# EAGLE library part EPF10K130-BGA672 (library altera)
EPF10K130 FLEX 10K family
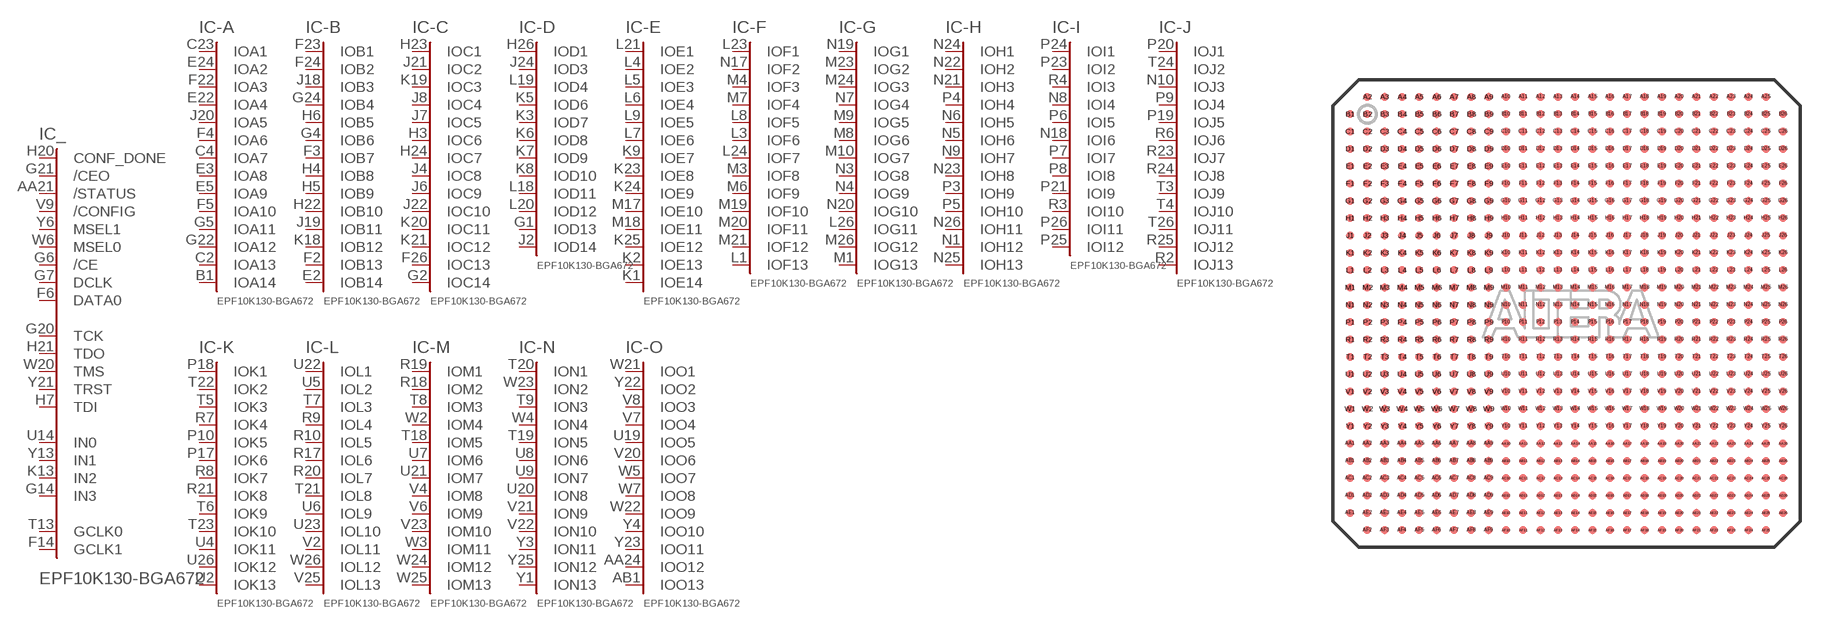
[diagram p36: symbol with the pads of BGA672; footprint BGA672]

Designator prefix IC; gates _=130E672C -A=A14-130E -B=B14-130E -C=C14-130E -D=D14-130E -E=E14-130E -F=F13-130E -G=G13-130E -H=H13-130E -I=I12-130E -J=J13-130E -K=K13-130E -L=L13-130E -M=M13-130E -N=N13-130E -O=O13-130E -P=P13-130E -1=51-130E -2=92-130E -3=133-130E -4=174-130E -5=221-130E -6=261-130E -7=301-130E -8=344-130E -9=384-130E -10=432-130E -11=472-130E -12=513-130E -13=524-130E G1=GND G2=GND G3=GND G4=GND G5=GND G6=GND G7=GND G8=GND G9=GND G10=GND G11=GND G12=GND G13=GND G14=GND G15=GND G16=GND G17=GND G18=GND G19=GND G20=GND G21=GND G22=GND G23=GND G24=GND G25=GND G26=GND G27=GND G28=GND G29=GND G30=GND G31=GND G32=GND G33=GND G34=GND G35=GND G36=GND G37=GND G38=GND G39=GND G40=GND G41=GND G42=GND G43=GND G44=GND G45=GND G46=GND G47=GND G48=GND G49=GND G50=GND G51=GND G52=GND G53=GND G54=GND G55=GND G56=GND G57=GND V1=VCCINT V2=VCCINT V3=VCCINT V4=VCCINT V5=VCCINT V6=VCCINT V7=VCCINT V8=VCCINT V9=VCCINT V10=VCCINT V11=VCCINT V12=VCCINT V13=VCCINT V14=VCCINT V15=VCCINT V16=VCCINT V17=VCCINT V18=VCCINT V19=VCCINT V20=VCCINT V21=VCCINT V22=VCCINT V23=VCCINT V24=VCCINT V25=VCCINT V26=VCCINT V27=VCCINT V28=VCCINT V29=VCCINT V30=VCCIO V31=VCCIO V32=VCCIO V33=VCCIO V34=VCCIO V35=VCCIO V36=VCCIO V37=VCCIO V38=VCCIO V39=VCCIO V40=VCCIO V41=VCCIO V42=VCCIO V43=VCCIO V44=VCCIO V45=VCCIO V46=VCCIO V47=VCCIO V48=VCCIO V49=VCCIO V50=VCCIO V51=VCCIO V52=VCCIO V53=VCCIO V54=VCCIO V55=VCCIO V56=VCCIO V57=VCCIO V58=VCCIO V59=VCCIO V60=VCCIO 1=NC 2=NC 3=NC 4=NC 5=NC 6=NC 7=NC 8=NC 9=NC 10=NC 11=NC 12=NC 13=NC 14=NC 15=NC 16=NC 17=NC 18=NC 19=NC 20=NC 21=NC 22=NC 23=NC 24=NC 25=NC 26=NC 27=NC 28=NC 29=NC 30=NC 31=NC 32=NC 33=NC 34=NC 35=NC 36=NC 37=NC 38=NC 39=NC 40=NC 41=NC 42=NC 43=NC 44=NC 45=NC 46=NC 47=NC 48=NC 49=NC 50=NC 51=NC 52=NC 53=NC 54=NC 55=NC 56=NC 57=NC 58=NC 59=NC 60=NC 61=NC 62=NC 63=NC 64=NC 65=NC 66=NC 67=NC 68=NC 69=NC 70=NC 71=NC 72=NC 73=NC 74=NC 75=NC 76=NC 77=NC 78=NC 79=NC 80=NC 81=NC 82=NC 83=NC 84=NC 85=NC 86=NC 87=NC 88=NC 89=NC 90=NC 91=NC 92=NC 93=NC 94=NC 95=NC 96=NC 97=NC 98=NC 99=NC 100=NC 101=NC 102=NC 103=NC 104=NC 105=NC 106=NC 107=NC 108=NC 109=NC 110=NC 111=NC 112=NC 113=NC 114=NC 115=NC 116=NC 117=NC 118=NC 119=NC 120=NC 121=NC 122=NC 123=NC 124=NC 125=NC 126=NC 127=NC 128=NC

## EPF10K130-BGA672 (MPN: EPF10K130EFC672-1; OC_FARNELL: unknown; OC_NEWARK: 51R8863)  [BGA672]
A2  G17:GND  pwr
A3  55:NC  nc
A4  56:NC  nc
A5  57:NC  nc
A6  58:NC  nc
A7  -2:IO64
A8  59:NC  nc
A9  60:NC  nc
A10  61:NC  nc
A11  62:NC  nc
A12  63:NC  nc
A13  64:NC  nc
A14  65:NC  nc
A15  66:NC  nc
A16  67:NC  nc
A17  68:NC  nc
A18  69:NC  nc
A19  70:NC  nc
A20  71:NC  nc
A21  72:NC  nc
A22  73:NC  nc
A23  74:NC  nc
A24  75:NC  nc
A25  G18:GND  pwr
AA1  1:NC  nc
AA2  2:NC  nc
AA3  -P:IOP12
AA4  -P:IOP5
AA5  -P:IOP3
AA6  -P:IOP4
AA7  -1:IO43
AA8  -2:IO71
AA9  -3:IO101
AA10  -3:IO131
AA11  -4:IO161
AA12  -6:IO223
AA13  G1:GND  pwr
AA14  -7:IO271
AA15  -8:IO323
AA16  -9:IO351
AA17  -10:IO392
AA18  -11:IO434
AA19  -12:IO483
AA20  -12:IO504
AA21  _:/STATUS  in
AA22  G2:GND  pwr
AA23  V1:VCC  pwr
AA24  -O:IOO12
AA25  3:NC  nc
AA26  V30:VCCIO  pwr
AB1  -O:IOO13
AB2  4:NC  nc
AB3  G3:GND  pwr
AB4  G4:GND  pwr
AB5  G5:GND  pwr
AB6  -1:IO14
AB7  -2:IO63
AB8  -2:IO81
AB9  -3:IO104
AB10  V2:VCC  pwr
AB11  -5:IO184
AB12  -6:IO224
AB13  -6:IO251
AB14  -7:IO284
AB15  -8:IO314
AB16  -9:IO354
AB17  -9:IO381
AB18  -10:IO414
AB19  -11:IO454
AB20  -12:IO481
AB21  -13:IO514
AB22  -13:IO521
AB23  G6:GND  pwr
AB24  G7:GND  pwr
AB25  5:NC  nc
AB26  6:NC  nc
AC1  7:NC  nc
AC2  8:NC  nc
AC3  G8:GND  pwr
AC4  -1:IO22
AC5  -1:IO21
AC6  -1:IO32
AC7  -2:IO61
AC8  G9:GND  pwr
AC9  -4:IO144
AC10  -4:IO164
AC11  -5:IO191
AC12  -6:IO234
AC13  -7:IO264
AC14  V3:VCC  pwr
AC15  -7:IO291
AC16  -8:IO342
AC17  -9:IO372
AC18  -10:IO402
AC19  -10:IO431
AC20  -11:IO461
AC21  -12:IO491
AC22  -12:IO511
AC23  -P:IOP6
AC24  G10:GND  pwr
AC25  9:NC  nc
AC26  10:NC  nc
AD1  -P:IOP13
AD2  11:NC  nc
AD3  -1:IO11
AD4  -1:IO31
AD5  -1:IO41
AD6  -1:IO51
AD7  -2:IO82
AD8  -3:IO121
AD9  -4:IO141
AD10  -4:IO172
AD11  -5:IO201
AD12  -6:IO231
AD13  G11:GND  pwr
AD14  -7:IO272
AD15  V31:VCCIO  pwr
AD16  -8:IO321
AD17  -9:IO364
AD18  G12:GND  pwr
AD19  -10:IO412
AD20  -11:IO442
AD21  -11:IO472
AD22  -12:IO503
AD23  -13:IO523
AD24  -P:IOP7
AD25  -P:IOP1
AD26  12:NC  nc
AE1  13:NC  nc
AE2  G13:GND  pwr
AE3  14:NC  nc
AE4  15:NC  nc
AE5  16:NC  nc
AE6  17:NC  nc
AE7  18:NC  nc
AE8  19:NC  nc
AE9  20:NC  nc
AE10  21:NC  nc
AE11  22:NC  nc
AE12  23:NC  nc
AE13  -6:IO261
AE14  24:NC  nc
AE15  25:NC  nc
AE16  26:NC  nc
AE17  27:NC  nc
AE18  -9:IO384
AE19  28:NC  nc
AE20  29:NC  nc
AE21  30:NC  nc
AE22  31:NC  nc
AE23  32:NC  nc
AE24  33:NC  nc
AE25  G14:GND  pwr
AE26  34:NC  nc
AF2  G15:GND  pwr
AF3  35:NC  nc
AF4  36:NC  nc
AF5  37:NC  nc
AF6  38:NC  nc
AF7  39:NC  nc
AF8  40:NC  nc
AF9  41:NC  nc
AF10  42:NC  nc
AF11  43:NC  nc
AF12  44:NC  nc
AF13  45:NC  nc
AF14  46:NC  nc
AF15  47:NC  nc
AF16  48:NC  nc
AF17  49:NC  nc
AF18  50:NC  nc
AF19  -10:IO394
AF20  51:NC  nc
AF21  52:NC  nc
AF22  -11:IO464
AF23  53:NC  nc
AF24  54:NC  nc
AF25  G16:GND  pwr
B1  -A:IOA14
B2  G19:GND  pwr
B3  76:NC  nc
B4  77:NC  nc
B5  78:NC  nc
B6  79:NC  nc
B7  80:NC  nc
B8  81:NC  nc
B9  82:NC  nc
B10  83:NC  nc
B11  84:NC  nc
B12  85:NC  nc
B13  86:NC  nc
B14  87:NC  nc
B15  -7:IO294
B16  88:NC  nc
B17  -8:IO344
B18  -10:IO393
B19  89:NC  nc
B20  90:NC  nc
B21  91:NC  nc
B22  92:NC  nc
B23  93:NC  nc
B24  94:NC  nc
B25  G20:GND  pwr
B26  95:NC  nc
C1  96:NC  nc
C2  -A:IOA13
C3  G21:GND  pwr
C4  -A:IOA7
C5  -1:IO23
C6  -1:IO42
C7  -2:IO83
C8  V32:VCCIO  pwr
C9  -3:IO103
C10  G22:GND  pwr
C11  -5:IO182
C12  -5:IO212
C13  -6:IO252
C14  -7:IO274
C15  V33:VCCIO  pwr
C16  -8:IO322
C17  -9:IO362
C18  -10:IO391
C19  -10:IO422
C20  -11:IO463
C21  -11:IO471
C22  -12:IO513
C23  -A:IOA1
C24  G23:GND  pwr
C25  97:NC  nc
C26  98:NC  nc
D1  99:NC  nc
D2  100:NC  nc
D3  G24:GND  pwr
D4  G25:GND  pwr
D5  -1:IO12
D6  -1:IO24
D7  V34:VCCIO  pwr
D8  -2:IO72
D9  -3:IO122
D10  -4:IO153
D11  -5:IO192
D12  -6:IO222
D13  -7:IO262
D14  -7:IO282
D15  -7:IO293
D16  -8:IO333
D17  -9:IO371
D18  -10:IO403
D19  G26:GND  pwr
D20  -11:IO462
D21  -12:IO493
D22  -13:IO524
D23  G27:GND  pwr
D24  G28:GND  pwr
D25  101:NC  nc
D26  102:NC  nc
E1  103:NC  nc
E2  -B:IOB14
E3  -A:IOA8
E4  G29:GND  pwr
E5  -A:IOA9
E6  -1:IO13
E7  -2:IO52
E8  -2:IO73
E9  -3:IO93
E10  -3:IO133
E11  -4:IO173
E12  -5:IO221
E13  V4:VCC  pwr
E14  -7:IO283
E15  -8:IO312
E16  -9:IO352
E17  V5:VCC  pwr
E18  -11:IO433
E19  -11:IO453
E20  -12:IO482
E21  -12:IO501
E22  -A:IOA4
E23  G30:GND  pwr
E24  -A:IOA2
E25  104:NC  nc
E26  105:NC  nc
F1  106:NC  nc
F2  -B:IOB13
F3  -B:IOB7
F4  -A:IOA6
F5  -A:IOA10
F6  _:DATA0  in
F7  -3:IO102
F8  -2:IO62
F9  -3:IO132
F10  -4:IO142
F11  -4:IO171
F12  -5:IO213
F13  -6:IO253
F14  _:GCLK1  in
F15  -8:IO302
F16  -9:IO373
F17  -10:IO413
F18  -10:IO423
F19  -12:IO473
F20  -12:IO512
F21  -13:IO522
F22  -A:IOA3
F23  -B:IOB1
F24  -B:IOB2
F25  107:NC  nc
F26  -C:IOC13
G1  -D:IOD13
G2  -C:IOC14
G3  V35:VCCIO  pwr
G4  -B:IOB6
G5  -A:IOA11
G6  _:/CE  in
G7  _:DCLK  in
G8  -2:IO92
G9  -3:IO123
G10  -4:IO152
G11  -4:IO163
G12  -6:IO232
G13  -6:IO242
G14  _:IN3  in
G15  -8:IO313
G16  -9:IO383
G17  -10:IO432
G18  -11:IO441
G19  -12:IO502
G20  _:TCK
G21  _:/CEO  in
G22  -A:IOA12
G23  G31:GND  pwr
G24  -B:IOB4
G25  108:NC  nc
G26  109:NC  nc
H1  110:NC  nc
H2  V6:VCC  pwr
H3  -C:IOC6
H4  -B:IOB8
H5  -B:IOB9
H6  -B:IOB5
H7  _:TDI
H8  -3:IO112
H9  -1:IO33
H10  -2:IO84
H11  -4:IO162
H12  -5:IO193
H13  -6:IO233
H14  -7:IO273
H15  -8:IO343
H16  -9:IO382
H17  -11:IO443
H18  -11:IO452
H19  -12:IO492
H20  _:CONF_DONE  in
H21  _:TDO
H22  -B:IOB10
H23  -C:IOC1
H24  -C:IOC7
H25  V7:VCC  pwr
H26  -D:IOD1
J1  111:NC  nc
J2  -D:IOD14
J3  V36:VCCIO  pwr
J4  -C:IOC8
J5  G32:GND  pwr
J6  -C:IOC9
J7  -C:IOC5
J8  -C:IOC4
J9  -4:IO143
J10  -1:IO34
J11  -2:IO53
J12  -5:IO203
J13  -7:IO263
J14  -6:IO243
J15  -9:IO353
J16  -10:IO411
J17  V37:VCCIO  pwr
J18  -B:IOB3
J19  -B:IOB11
J20  -A:IOA5
J21  -C:IOC2
J22  -C:IOC10
J23  G33:GND  pwr
J24  -D:IOD3
J25  112:NC  nc
J26  113:NC  nc
K1  -E:IOE14
K2  -E:IOE13
K3  -D:IOD7
K4  G34:GND  pwr
K5  -D:IOD6
K6  -D:IOD8
K7  -D:IOD9
K8  -D:IOD10
K9  -E:IOE7
K10  G35:GND  pwr
K11  V38:VCCIO  pwr
K12  -5:IO183
K13  _:IN2  in
K14  -5:IO202
K15  -9:IO363
K16  V8:VCC  pwr
K17  G36:GND  pwr
K18  -B:IOB12
K19  -C:IOC3
K20  -C:IOC11
K21  -C:IOC12
K22  V39:VCCIO  pwr
K23  -E:IOE8
K24  -E:IOE9
K25  -E:IOE12
K26  114:NC  nc
L1  -F:IOF13
L2  115:NC  nc
L3  -F:IOF6
L4  -E:IOE2
L5  -E:IOE3
L6  -E:IOE4
L7  -E:IOE6
L8  -F:IOF5
L9  -E:IOE5
L10  V9:VCC  pwr
L11  G37:GND  pwr
L12  V10:VCC  pwr
L13  V40:VCCIO  pwr
L14  V11:VCC  pwr
L15  V41:VCCIO  pwr
L16  G38:GND  pwr
L17  V12:VCC  pwr
L18  -D:IOD11
L19  -D:IOD4
L20  -D:IOD12
L21  -E:IOE1
L22  G39:GND  pwr
L23  -F:IOF1
L24  -F:IOF7
L25  116:NC  nc
L26  -G:IOG11
M1  -G:IOG13
M2  V13:VCC  pwr
M3  -F:IOF8
M4  -F:IOF3
M5  G40:GND  pwr
M6  -F:IOF9
M7  -F:IOF4
M8  -G:IOG6
M9  -G:IOG5
M10  -G:IOG7
M11  V42:VCCIO  pwr
M12  G41:GND  pwr
M13  V43:VCCIO  pwr
M14  G42:GND  pwr
M15  G43:GND  pwr
M16  V44:VCCIO  pwr
M17  -E:IOE10
M18  -E:IOE11
M19  -F:IOF10
M20  -F:IOF11
M21  -F:IOF12
M22  V45:VCCIO  pwr
M23  -G:IOG2
M24  -G:IOG3
M25  V14:VCC  pwr
M26  -G:IOG12
N1  -H:IOH12
N2  117:NC  nc
N3  -G:IOG8
N4  -G:IOG9
N5  -H:IOH6
N6  -H:IOH5
N7  -G:IOG4
N8  -I:IOI4
N9  -H:IOH7
N10  -J:IOJ3
N11  V15:VCC  pwr
N12  V16:VCC  pwr
N13  G44:GND  pwr
N14  G45:GND  pwr
N15  V17:VCC  pwr
N16  V46:VCCIO  pwr
N17  -F:IOF2
N18  -I:IOI6
N19  -G:IOG1
N20  -G:IOG10
N21  -H:IOH3
N22  -H:IOH2
N23  -H:IOH8
N24  -H:IOH1
N25  -H:IOH13
N26  -H:IOH11
P1  118:NC  nc
P2  119:NC  nc
P3  -H:IOH9
P4  -H:IOH4
P5  -H:IOH10
P6  -I:IOI5
P7  -I:IOI7
P8  -I:IOI8
P9  -J:IOJ4
P10  -K:IOK5
P11  V47:VCCIO  pwr
P12  V18:VCC  pwr
P13  G46:GND  pwr
P14  G47:GND  pwr
P15  V19:VCC  pwr
P16  V20:VCC  pwr
P17  -K:IOK6
P18  -K:IOK1
P19  -J:IOJ5
P20  -J:IOJ1
P21  -I:IOI9
P22  G48:GND  pwr
P23  -I:IOI2
P24  -I:IOI1
P25  -I:IOI12
P26  -I:IOI11
R1  120:NC  nc
R2  -J:IOJ13
R3  -I:IOI10
R4  -I:IOI3
R5  V48:VCCIO  pwr
R6  -J:IOJ6
R7  -K:IOK4
R8  -K:IOK7
R9  -L:IOL4
R10  -L:IOL5
R11  V49:VCCIO  pwr
R12  G49:GND  pwr
R13  V50:VCCIO  pwr
R14  V21:VCC  pwr
R15  G50:GND  pwr
R16  V51:VCCIO  pwr
R17  -L:IOL6
R18  -M:IOM2
R19  -M:IOM1
R20  -L:IOL7
R21  -K:IOK8
R22  V52:VCCIO  pwr
R23  -J:IOJ7
R24  -J:IOJ8
R25  -J:IOJ12
R26  121:NC  nc
T1  122:NC  nc
T2  V22:VCC  pwr
T3  -J:IOJ9
T4  -J:IOJ10
T5  -K:IOK3
T6  -K:IOK9
T7  -L:IOL3
T8  -M:IOM3
T9  -N:ION3
T10  V23:VCC  pwr
T11  G51:GND  pwr
T12  V24:VCC  pwr
T13  _:GCLK0  in
T14  V25:VCC  pwr
T15  V53:VCCIO  pwr
T16  G52:GND  pwr
T17  V26:VCC  pwr
T18  -M:IOM5
T19  -N:ION5
T20  -N:ION1
T21  -L:IOL8
T22  -K:IOK2
T23  -K:IOK10
T24  -J:IOJ2
T25  V27:VCC  pwr
T26  -J:IOJ11
U1  123:NC  nc
U2  -K:IOK13
U3  V54:VCCIO  pwr
U4  -K:IOK11
U5  -L:IOL2
U6  -L:IOL9
U7  -M:IOM6
U8  -N:ION6
U9  -N:ION7
U10  G53:GND  pwr
U11  V55:VCCIO  pwr
U12  -4:IO151
U13  -6:IO244
U14  _:IN0  in
U15  -7:IO301
U16  V28:VCC  pwr
U17  G54:GND  pwr
U18  -P:IOP8
U19  -O:IOO5
U20  -N:ION8
U21  -M:IOM7
U22  -L:IOL1
U23  -L:IOL10
U24  G55:GND  pwr
U25  124:NC  nc
U26  -K:IOK12
V1  125:NC  nc
V2  -L:IOL11
V3  G56:GND  pwr
V4  -M:IOM8
V5  V56:VCCIO  pwr
V6  -M:IOM9
V7  -O:IOO4
V8  -O:IOO3
V9  _:/CONFIG  in
V10  -3:IO111
V11  -4:IO154
V12  -5:IO204
V13  -6:IO241
V14  -8:IO303
V15  -8:IO331
V16  -10:IO421
V17  V57:VCCIO  pwr
V18  -P:IOP9
V19  -P:IOP10
V20  -O:IOO6
V21  -N:ION9
V22  -N:ION10
V23  -M:IOM10
V24  V58:VCCIO  pwr
V25  -L:IOL13
V26  126:NC  nc
W1  127:NC  nc
W2  -M:IOM4
W3  -M:IOM11
W4  -N:ION4
W5  -O:IOO7
W6  _:MSEL0  in
W7  -O:IOO8
W8  -P:IOP11
W9  -3:IO94
W10  -3:IO113
W11  -5:IO181
W12  -5:IO214
W13  -6:IO254
W14  -7:IO292
W15  -8:IO332
W16  -9:IO374
W17  -9:IO361
W18  -11:IO451
W19  -12:IO474
W20  _:TMS
W21  -O:IOO1
W22  -O:IOO9
W23  -N:ION2
W24  -M:IOM12
W25  -M:IOM13
W26  -L:IOL12
Y1  -N:ION13
Y2  V59:VCCIO  pwr
Y3  -N:ION11
Y4  -O:IOO10
Y5  G57:GND  pwr
Y6  _:MSEL1  in
Y7  V29:VCC  pwr
Y8  -2:IO74
Y9  -2:IO91
Y10  -3:IO124
Y11  -4:IO174
Y12  -5:IO211
Y13  _:IN1  in
Y14  -7:IO281
Y15  -8:IO311
Y16  -8:IO341
Y17  -10:IO401
Y18  -11:IO444
Y19  -12:IO494
Y20  -P:IOP2
Y21  _:TRST
Y22  -O:IOO2
Y23  -O:IOO11
Y24  V60:VCCIO  pwr
Y25  -N:ION12
Y26  128:NC  nc

## Footprint BGA672 (pad centres in mm)
Ball Grid Array
smd 0.45 x 0.45: A2 -11.5,12.5; A3 -10.5,12.5; A4 -9.5,12.5; A5 -8.5,12.5; A6 -7.5,12.5; A7 -6.5,12.5; A8 -5.5,12.5; A9 -4.5,12.5; A10 -3.5,12.5; A11 -2.5,12.5; A12 -1.5,12.5; A13 -0.5,12.5; A14 0.5,12.5; A15 1.5,12.5; A16 2.5,12.5; A17 3.5,12.5; A18 4.5,12.5; A19 5.5,12.5; A20 6.5,12.5; A21 7.5,12.5; A22 8.5,12.5; A23 9.5,12.5; A24 10.5,12.5; A25 11.5,12.5; AA1 -12.5,-7.5; AA2 -11.5,-7.5; AA3 -10.5,-7.5; AA4 -9.5,-7.5; AA5 -8.5,-7.5; AA6 -7.5,-7.5; AA7 -6.5,-7.5; AA8 -5.5,-7.5; AA9 -4.5,-7.5; AA10 -3.5,-7.5; AA11 -2.5,-7.5; AA12 -1.5,-7.5; AA13 -0.5,-7.5; AA14 0.5,-7.5; AA15 1.5,-7.5; AA16 2.5,-7.5; AA17 3.5,-7.5; AA18 4.5,-7.5; AA19 5.5,-7.5; AA20 6.5,-7.5; AA21 7.5,-7.5; AA22 8.5,-7.5; AA23 9.5,-7.5; AA24 10.5,-7.5; AA25 11.5,-7.5; AA26 12.5,-7.5; AB1 -12.5,-8.5; AB2 -11.5,-8.5; AB3 -10.5,-8.5; AB4 -9.5,-8.5; AB5 -8.5,-8.5; AB6 -7.5,-8.5; AB7 -6.5,-8.5; AB8 -5.5,-8.5; AB9 -4.5,-8.5; AB10 -3.5,-8.5; AB11 -2.5,-8.5; AB12 -1.5,-8.5; AB13 -0.5,-8.5; AB14 0.5,-8.5; AB15 1.5,-8.5; AB16 2.5,-8.5; AB17 3.5,-8.5; AB18 4.5,-8.5; AB19 5.5,-8.5; AB20 6.5,-8.5; AB21 7.5,-8.5; AB22 8.5,-8.5; AB23 9.5,-8.5; AB24 10.5,-8.5; AB25 11.5,-8.5; AB26 12.5,-8.5; AC1 -12.5,-9.5; AC2 -11.5,-9.5; AC3 -10.5,-9.5; AC4 -9.5,-9.5; AC5 -8.5,-9.5; AC6 -7.5,-9.5; AC7 -6.5,-9.5; AC8 -5.5,-9.5; AC9 -4.5,-9.5; AC10 -3.5,-9.5; AC11 -2.5,-9.5; AC12 -1.5,-9.5; AC13 -0.5,-9.5; AC14 0.5,-9.5; AC15 1.5,-9.5; AC16 2.5,-9.5; AC17 3.5,-9.5; AC18 4.5,-9.5; AC19 5.5,-9.5; AC20 6.5,-9.5; AC21 7.5,-9.5; AC22 8.5,-9.5; AC23 9.5,-9.5; AC24 10.5,-9.5; AC25 11.5,-9.5; AC26 12.5,-9.5; AD1 -12.5,-10.5; AD2 -11.5,-10.5; AD3 -10.5,-10.5; AD4 -9.5,-10.5; AD5 -8.5,-10.5; AD6 -7.5,-10.5; AD7 -6.5,-10.5; AD8 -5.5,-10.5; AD9 -4.5,-10.5; AD10 -3.5,-10.5; AD11 -2.5,-10.5; AD12 -1.5,-10.5; AD13 -0.5,-10.5; AD14 0.5,-10.5; AD15 1.5,-10.5; AD16 2.5,-10.5; AD17 3.5,-10.5; AD18 4.5,-10.5; AD19 5.5,-10.5; AD20 6.5,-10.5; AD21 7.5,-10.5; AD22 8.5,-10.5; AD23 9.5,-10.5; AD24 10.5,-10.5; AD25 11.5,-10.5; AD26 12.5,-10.5; AE1 -12.5,-11.5; AE2 -11.5,-11.5; AE3 -10.5,-11.5; AE4 -9.5,-11.5; AE5 -8.5,-11.5; AE6 -7.5,-11.5; AE7 -6.5,-11.5; AE8 -5.5,-11.5; AE9 -4.5,-11.5; AE10 -3.5,-11.5; AE11 -2.5,-11.5; AE12 -1.5,-11.5; AE13 -0.5,-11.5; AE14 0.5,-11.5; AE15 1.5,-11.5; AE16 2.5,-11.5; AE17 3.5,-11.5; AE18 4.5,-11.5; AE19 5.5,-11.5; AE20 6.5,-11.5; AE21 7.5,-11.5; AE22 8.5,-11.5; AE23 9.5,-11.5; AE24 10.5,-11.5; AE25 11.5,-11.5; AE26 12.5,-11.5; AF2 -11.5,-12.5; AF3 -10.5,-12.5; AF4 -9.5,-12.5; AF5 -8.5,-12.5; AF6 -7.5,-12.5; AF7 -6.5,-12.5; AF8 -5.5,-12.5; AF9 -4.5,-12.5; AF10 -3.5,-12.5; AF11 -2.5,-12.5; AF12 -1.5,-12.5; AF13 -0.5,-12.5; AF14 0.5,-12.5; AF15 1.5,-12.5; AF16 2.5,-12.5; AF17 3.5,-12.5; AF18 4.5,-12.5; AF19 5.5,-12.5; AF20 6.5,-12.5; AF21 7.5,-12.5; AF22 8.5,-12.5; AF23 9.5,-12.5; AF24 10.5,-12.5; AF25 11.5,-12.5; B1 -12.5,11.5; B2 -11.5,11.5; B3 -10.5,11.5; B4 -9.5,11.5; B5 -8.5,11.5; B6 -7.5,11.5; B7 -6.5,11.5; B8 -5.5,11.5; B9 -4.5,11.5; B10 -3.5,11.5; B11 -2.5,11.5; B12 -1.5,11.5; B13 -0.5,11.5; B14 0.5,11.5; B15 1.5,11.5; B16 2.5,11.5; B17 3.5,11.5; B18 4.5,11.5; B19 5.5,11.5; B20 6.5,11.5; B21 7.5,11.5; B22 8.5,11.5; B23 9.5,11.5; B24 10.5,11.5; B25 11.5,11.5; B26 12.5,11.5; C1 -12.5,10.5; C2 -11.5,10.5; C3 -10.5,10.5; C4 -9.5,10.5; C5 -8.5,10.5; C6 -7.5,10.5; C7 -6.5,10.5; C8 -5.5,10.5; C9 -4.5,10.5; C10 -3.5,10.5; C11 -2.5,10.5; C12 -1.5,10.5; C13 -0.5,10.5; C14 0.5,10.5; C15 1.5,10.5; C16 2.5,10.5; C17 3.5,10.5; C18 4.5,10.5; C19 5.5,10.5; C20 6.5,10.5; C21 7.5,10.5; C22 8.5,10.5; C23 9.5,10.5; C24 10.5,10.5; C25 11.5,10.5; C26 12.5,10.5; D1 -12.5,9.5; D2 -11.5,9.5; D3 -10.5,9.5; D4 -9.5,9.5; D5 -8.5,9.5; D6 -7.5,9.5; D7 -6.5,9.5; D8 -5.5,9.5; D9 -4.5,9.5; D10 -3.5,9.5; D11 -2.5,9.5; D12 -1.5,9.5; D13 -0.5,9.5; D14 0.5,9.5; D15 1.5,9.5; D16 2.5,9.5; D17 3.5,9.5; D18 4.5,9.5; D19 5.5,9.5; D20 6.5,9.5; D21 7.5,9.5; D22 8.5,9.5; D23 9.5,9.5; D24 10.5,9.5; D25 11.5,9.5; D26 12.5,9.5; E1 -12.5,8.5; E2 -11.5,8.5; E3 -10.5,8.5; E4 -9.5,8.5; E5 -8.5,8.5; E6 -7.5,8.5; E7 -6.5,8.5; E8 -5.5,8.5; E9 -4.5,8.5; E10 -3.5,8.5; E11 -2.5,8.5; E12 -1.5,8.5; E13 -0.5,8.5; E14 0.5,8.5; E15 1.5,8.5; E16 2.5,8.5; E17 3.5,8.5; E18 4.5,8.5; E19 5.5,8.5; E20 6.5,8.5; E21 7.5,8.5; E22 8.5,8.5; E23 9.5,8.5; E24 10.5,8.5; E25 11.5,8.5; E26 12.5,8.5; F1 -12.5,7.5; F2 -11.5,7.5; F3 -10.5,7.5; F4 -9.5,7.5; F5 -8.5,7.5; F6 -7.5,7.5; F7 -6.5,7.5; F8 -5.5,7.5; F9 -4.5,7.5; F10 -3.5,7.5; F11 -2.5,7.5; F12 -1.5,7.5; F13 -0.5,7.5; F14 0.5,7.5; F15 1.5,7.5; F16 2.5,7.5; F17 3.5,7.5; F18 4.5,7.5; F19 5.5,7.5; F20 6.5,7.5; F21 7.5,7.5; F22 8.5,7.5; F23 9.5,7.5; F24 10.5,7.5; F25 11.5,7.5; F26 12.5,7.5; G1 -12.5,6.5; G2 -11.5,6.5; G3 -10.5,6.5; G4 -9.5,6.5; G5 -8.5,6.5; G6 -7.5,6.5; G7 -6.5,6.5; G8 -5.5,6.5; G9 -4.5,6.5; G10 -3.5,6.5; G11 -2.5,6.5; G12 -1.5,6.5; G13 -0.5,6.5; G14 0.5,6.5; G15 1.5,6.5; G16 2.5,6.5; G17 3.5,6.5; G18 4.5,6.5; G19 5.5,6.5; G20 6.5,6.5; G21 7.5,6.5; G22 8.5,6.5; G23 9.5,6.5; G24 10.5,6.5; G25 11.5,6.5; G26 12.5,6.5; H1 -12.5,5.5; H2 -11.5,5.5; H3 -10.5,5.5; H4 -9.5,5.5; H5 -8.5,5.5; H6 -7.5,5.5; H7 -6.5,5.5; H8 -5.5,5.5; H9 -4.5,5.5; H10 -3.5,5.5; H11 -2.5,5.5; H12 -1.5,5.5; H13 -0.5,5.5; H14 0.5,5.5; H15 1.5,5.5; H16 2.5,5.5; H17 3.5,5.5; H18 4.5,5.5; H19 5.5,5.5; H20 6.5,5.5; H21 7.5,5.5; H22 8.5,5.5; H23 9.5,5.5; H24 10.5,5.5; H25 11.5,5.5; H26 12.5,5.5; J1 -12.5,4.5; J2 -11.5,4.5; J3 -10.5,4.5; J4 -9.5,4.5; J5 -8.5,4.5; J6 -7.5,4.5; J7 -6.5,4.5; J8 -5.5,4.5; J9 -4.5,4.5; J10 -3.5,4.5; J11 -2.5,4.5; J12 -1.5,4.5; J13 -0.5,4.5; J14 0.5,4.5; J15 1.5,4.5; J16 2.5,4.5; J17 3.5,4.5; J18 4.5,4.5; J19 5.5,4.5; J20 6.5,4.5; J21 7.5,4.5; J22 8.5,4.5; J23 9.5,4.5; J24 10.5,4.5; J25 11.5,4.5; J26 12.5,4.5; K1 -12.5,3.5; K2 -11.5,3.5; K3 -10.5,3.5; K4 -9.5,3.5; K5 -8.5,3.5; K6 -7.5,3.5; K7 -6.5,3.5; K8 -5.5,3.5; K9 -4.5,3.5; K10 -3.5,3.5; K11 -2.5,3.5; K12 -1.5,3.5; K13 -0.5,3.5; K14 0.5,3.5; K15 1.5,3.5; K16 2.5,3.5; K17 3.5,3.5; K18 4.5,3.5; K19 5.5,3.5; K20 6.5,3.5; K21 7.5,3.5; K22 8.5,3.5; K23 9.5,3.5; K24 10.5,3.5; K25 11.5,3.5; K26 12.5,3.5; L1 -12.5,2.5; L2 -11.5,2.5; L3 -10.5,2.5; L4 -9.5,2.5; L5 -8.5,2.5; L6 -7.5,2.5; L7 -6.5,2.5; L8 -5.5,2.5; L9 -4.5,2.5; L10 -3.5,2.5; L11 -2.5,2.5; L12 -1.5,2.5; L13 -0.5,2.5; L14 0.5,2.5; L15 1.5,2.5; L16 2.5,2.5; L17 3.5,2.5; L18 4.5,2.5; L19 5.5,2.5; L20 6.5,2.5; L21 7.5,2.5; L22 8.5,2.5; L23 9.5,2.5; L24 10.5,2.5; L25 11.5,2.5; L26 12.5,2.5; M1 -12.5,1.5; M2 -11.5,1.5; M3 -10.5,1.5; M4 -9.5,1.5; M5 -8.5,1.5; M6 -7.5,1.5; M7 -6.5,1.5; M8 -5.5,1.5; M9 -4.5,1.5; M10 -3.5,1.5; M11 -2.5,1.5; M12 -1.5,1.5; M13 -0.5,1.5; M14 0.5,1.5; M15 1.5,1.5; M16 2.5,1.5; M17 3.5,1.5; M18 4.5,1.5; M19 5.5,1.5; M20 6.5,1.5; M21 7.5,1.5; M22 8.5,1.5; M23 9.5,1.5; M24 10.5,1.5; M25 11.5,1.5; M26 12.5,1.5; N1 -12.5,0.5; N2 -11.5,0.5; N3 -10.5,0.5; N4 -9.5,0.5; N5 -8.5,0.5; N6 -7.5,0.5; N7 -6.5,0.5; N8 -5.5,0.5; N9 -4.5,0.5; N10 -3.5,0.5; N11 -2.5,0.5; N12 -1.5,0.5; N13 -0.5,0.5; N14 0.5,0.5; N15 1.5,0.5; N16 2.5,0.5; N17 3.5,0.5; N18 4.5,0.5; N19 5.5,0.5; N20 6.5,0.5; N21 7.5,0.5; N22 8.5,0.5; N23 9.5,0.5; N24 10.5,0.5; N25 11.5,0.5; N26 12.5,0.5; P1 -12.5,-0.5; P2 -11.5,-0.5; P3 -10.5,-0.5; P4 -9.5,-0.5; P5 -8.5,-0.5; P6 -7.5,-0.5; P7 -6.5,-0.5; P8 -5.5,-0.5; P9 -4.5,-0.5; P10 -3.5,-0.5; P11 -2.5,-0.5; P12 -1.5,-0.5; P13 -0.5,-0.5; P14 0.5,-0.5; P15 1.5,-0.5; P16 2.5,-0.5; P17 3.5,-0.5; P18 4.5,-0.5; P19 5.5,-0.5; P20 6.5,-0.5; P21 7.5,-0.5; P22 8.5,-0.5; P23 9.5,-0.5; P24 10.5,-0.5; P25 11.5,-0.5; P26 12.5,-0.5; R1 -12.5,-1.5; R2 -11.5,-1.5; R3 -10.5,-1.5; R4 -9.5,-1.5; R5 -8.5,-1.5; R6 -7.5,-1.5; R7 -6.5,-1.5; R8 -5.5,-1.5; R9 -4.5,-1.5; R10 -3.5,-1.5; R11 -2.5,-1.5; R12 -1.5,-1.5; R13 -0.5,-1.5; R14 0.5,-1.5; R15 1.5,-1.5; R16 2.5,-1.5; R17 3.5,-1.5; R18 4.5,-1.5; R19 5.5,-1.5; R20 6.5,-1.5; R21 7.5,-1.5; R22 8.5,-1.5; R23 9.5,-1.5; R24 10.5,-1.5; R25 11.5,-1.5; R26 12.5,-1.5; T1 -12.5,-2.5; T2 -11.5,-2.5; T3 -10.5,-2.5; T4 -9.5,-2.5; T5 -8.5,-2.5; T6 -7.5,-2.5; T7 -6.5,-2.5; T8 -5.5,-2.5; T9 -4.5,-2.5; T10 -3.5,-2.5; T11 -2.5,-2.5; T12 -1.5,-2.5; T13 -0.5,-2.5; T14 0.5,-2.5; T15 1.5,-2.5; T16 2.5,-2.5; T17 3.5,-2.5; T18 4.5,-2.5; T19 5.5,-2.5; T20 6.5,-2.5; T21 7.5,-2.5; T22 8.5,-2.5; T23 9.5,-2.5; T24 10.5,-2.5; T25 11.5,-2.5; T26 12.5,-2.5; U1 -12.5,-3.5; U2 -11.5,-3.5; U3 -10.5,-3.5; U4 -9.5,-3.5; U5 -8.5,-3.5; U6 -7.5,-3.5; U7 -6.5,-3.5; U8 -5.5,-3.5; U9 -4.5,-3.5; U10 -3.5,-3.5; U11 -2.5,-3.5; U12 -1.5,-3.5; U13 -0.5,-3.5; U14 0.5,-3.5; U15 1.5,-3.5; U16 2.5,-3.5; U17 3.5,-3.5; U18 4.5,-3.5; U19 5.5,-3.5; U20 6.5,-3.5; U21 7.5,-3.5; U22 8.5,-3.5; U23 9.5,-3.5; U24 10.5,-3.5; U25 11.5,-3.5; U26 12.5,-3.5; V1 -12.5,-4.5; V2 -11.5,-4.5; V3 -10.5,-4.5; V4 -9.5,-4.5; V5 -8.5,-4.5; V6 -7.5,-4.5; V7 -6.5,-4.5; V8 -5.5,-4.5; V9 -4.5,-4.5; V10 -3.5,-4.5; V11 -2.5,-4.5; V12 -1.5,-4.5; V13 -0.5,-4.5; V14 0.5,-4.5; V15 1.5,-4.5; V16 2.5,-4.5; V17 3.5,-4.5; V18 4.5,-4.5; V19 5.5,-4.5; V20 6.5,-4.5; V21 7.5,-4.5; V22 8.5,-4.5; V23 9.5,-4.5; V24 10.5,-4.5; V25 11.5,-4.5; V26 12.5,-4.5; W1 -12.5,-5.5; W2 -11.5,-5.5; W3 -10.5,-5.5; W4 -9.5,-5.5; W5 -8.5,-5.5; W6 -7.5,-5.5; W7 -6.5,-5.5; W8 -5.5,-5.5; W9 -4.5,-5.5; W10 -3.5,-5.5; W11 -2.5,-5.5; W12 -1.5,-5.5; W13 -0.5,-5.5; W14 0.5,-5.5; W15 1.5,-5.5; W16 2.5,-5.5; W17 3.5,-5.5; W18 4.5,-5.5; W19 5.5,-5.5; W20 6.5,-5.5; W21 7.5,-5.5; W22 8.5,-5.5; W23 9.5,-5.5; W24 10.5,-5.5; W25 11.5,-5.5; W26 12.5,-5.5; Y1 -12.5,-6.5; Y2 -11.5,-6.5; Y3 -10.5,-6.5; Y4 -9.5,-6.5; Y5 -8.5,-6.5; Y6 -7.5,-6.5; Y7 -6.5,-6.5; Y8 -5.5,-6.5; Y9 -4.5,-6.5; Y10 -3.5,-6.5; Y11 -2.5,-6.5; Y12 -1.5,-6.5; Y13 -0.5,-6.5; Y14 0.5,-6.5; Y15 1.5,-6.5; Y16 2.5,-6.5; Y17 3.5,-6.5; Y18 4.5,-6.5; Y19 5.5,-6.5; Y20 6.5,-6.5; Y21 7.5,-6.5; Y22 8.5,-6.5; Y23 9.5,-6.5; Y24 10.5,-6.5; Y25 11.5,-6.5; Y26 12.5,-6.5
